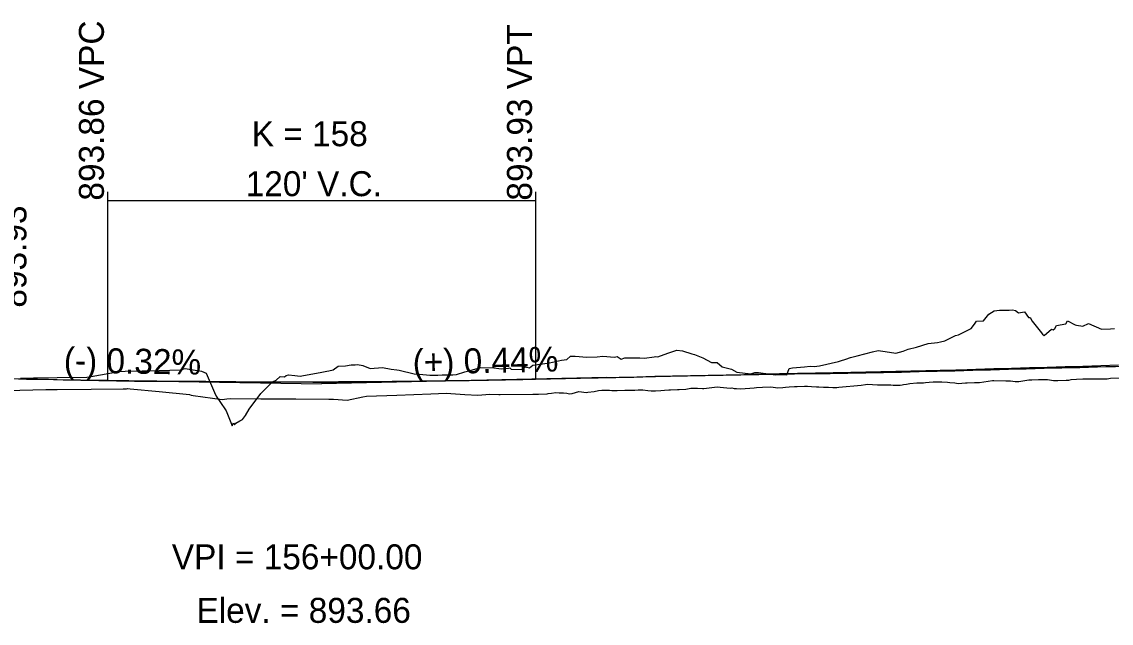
# Model space of a CAD drawing. Extents: x 1475774 to 1484571, y 1098511 to 1113011.
# Drawn here: x 1478287 to 1478592.4, y 1103912.5 to 1104081 of the extents above; entities that cross this region are included whole.
import ezdxf

# ---------------------------------------------------------------- set-up
doc = ezdxf.new("R2010")
doc.units = 0
for name, color, linetype in [('RD_DDB_GradeTX', 7, 'Continuous'), ('RD_DDB_PointTX', 7, 'Continuous'), ('RD_DDB_Profile_EX', 7, 'Continuous'), ('RD_DDB_Profile_Lbl', 7, 'Continuous'), ('RD_DDB_Profile_PR', 7, 'Continuous'), ('RD_DDB_StripGrade', 7, 'Continuous'), ('RD_DDB_VCLbl', 7, 'Continuous'), ('RD_Sketch2', 7, 'Continuous'), ('RD_Sketch3', 7, 'Continuous')]:
    doc.layers.add(name, color=color, linetype=linetype)

msp = doc.modelspace()

# ---------------------------------------------------------------- linework, layer by layer
at = {"layer": 'RD_DDB_GradeTX'}
for p in [(1478450.96, 1103981.31), (1478290.99, 1103980.85)]:
    msp.add_line(p, (1478370.98, 1103979.56), dxfattribs=at)
at = {"layer": 'RD_DDB_PointTX'}
msp.add_lwpolyline([(1478284.42, 1103981), (1478289.42, 1103980.88), (1478294.42, 1103980.81), (1478299.42, 1103980.7), (1478304.42, 1103980.58), (1478309.42, 1103980.46), (1478314.42, 1103980.34), (1478319.42, 1103980.32), (1478324.42, 1103980.3), (1478329.42, 1103980.28), (1478334.42, 1103980.26), (1478339.42, 1103980.24), (1478344.42, 1103980.14), (1478349.42, 1103980.12), (1478354.42, 1103980.1), (1478359.42, 1103980.09), (1478364.42, 1103980.07), (1478369.42, 1103980.04), (1478374.42, 1103980.02), (1478379.42, 1103980), (1478384.42, 1103980.01), (1478389.42, 1103980.1), (1478394.42, 1103980.2), (1478399.42, 1103980.3), (1478404.42, 1103980.39), (1478409.42, 1103980.48), (1478414.42, 1103980.58), (1478419.42, 1103980.68), (1478424.42, 1103980.78), (1478429.42, 1103980.88), (1478434.42, 1103980.98), (1478439.42, 1103981.09), (1478444.42, 1103981.2), (1478449.42, 1103981.31), (1478454.42, 1103981.42), (1478459.42, 1103981.54), (1478464.42, 1103981.65), (1478469.42, 1103981.76), (1478474.42, 1103981.87), (1478479.42, 1103981.98), (1478484.42, 1103982.1), (1478489.42, 1103982.2), (1478494.42, 1103982.3), (1478499.42, 1103982.4), (1478504.42, 1103982.5), (1478509.42, 1103982.6), (1478514.42, 1103982.7), (1478519.42, 1103982.79), (1478524.42, 1103982.89), (1478529.42, 1103982.99), (1478534.42, 1103983.09), (1478539.42, 1103983.22), (1478544.42, 1103983.36), (1478549.42, 1103983.51), (1478554.42, 1103983.65), (1478559.42, 1103983.8), (1478564.42, 1103983.94), (1478569.42, 1103984.09), (1478574.42, 1103984.23), (1478579.42, 1103984.38), (1478584.42, 1103984.53), (1478589.42, 1103984.69), (1478594.42, 1103984.84)], dxfattribs=at)
at = {"layer": 'RD_DDB_Profile_EX'}
msp.add_lwpolyline([(1478283.54, 1103981), (1478288.54, 1103980.88), (1478293.54, 1103980.81), (1478298.54, 1103980.7), (1478303.54, 1103980.58), (1478308.54, 1103980.46), (1478313.54, 1103980.34), (1478318.54, 1103980.32), (1478323.54, 1103980.3), (1478328.54, 1103980.28), (1478333.54, 1103980.27), (1478338.54, 1103980.25), (1478343.54, 1103980.14), (1478348.54, 1103980.12), (1478353.54, 1103980.11), (1478358.54, 1103980.09), (1478363.54, 1103980.07), (1478368.54, 1103980.03), (1478373.54, 1103980.02), (1478378.54, 1103980), (1478383.54, 1103980), (1478388.54, 1103980.09), (1478393.54, 1103980.19), (1478398.54, 1103980.28), (1478403.54, 1103980.38), (1478408.54, 1103980.45), (1478413.54, 1103980.55), (1478418.54, 1103980.64), (1478423.54, 1103980.74), (1478428.54, 1103980.83), (1478433.54, 1103980.91), (1478438.54, 1103981.01), (1478443.54, 1103981.12), (1478448.54, 1103981.23), (1478453.54, 1103981.33), (1478458.54, 1103981.44), (1478463.54, 1103981.55), (1478468.54, 1103981.65), (1478473.54, 1103981.76), (1478478.54, 1103981.86), (1478483.54, 1103981.97), (1478488.54, 1103982.04), (1478493.54, 1103982.13), (1478498.54, 1103982.23), (1478503.54, 1103982.32), (1478508.54, 1103982.42), (1478513.54, 1103982.48), (1478518.54, 1103982.57), (1478523.54, 1103982.66), (1478528.54, 1103982.75), (1478533.54, 1103982.85), (1478538.54, 1103982.96), (1478543.54, 1103983.1), (1478548.54, 1103983.23), (1478553.54, 1103983.36), (1478558.54, 1103983.5), (1478563.54, 1103983.63), (1478568.54, 1103983.76), (1478573.54, 1103983.89), (1478578.54, 1103984.02), (1478583.54, 1103984.15), (1478588.54, 1103984.3), (1478593.54, 1103984.44)], dxfattribs=at)
at = {"layer": 'RD_DDB_Profile_PR'}
for p, q in [((1478430.98, 1103980.88), (1479020.98, 1103993.81)), ((1478430.98, 1103980.88), (1479020.98, 1103993.81)), ((1478288.27, 1103980.89), (1478310.98, 1103980.53)), ((1478288.27, 1103980.89), (1478310.98, 1103980.53))]:
    msp.add_line(p, q, dxfattribs=at)
msp.add_spline([(1478310.98, 1103980.53), (1478313.38, 1103980.49), (1478315.78, 1103980.45), (1478318.18, 1103980.42), (1478320.58, 1103980.39), (1478322.98, 1103980.36), (1478325.38, 1103980.33), (1478327.78, 1103980.3), (1478330.18, 1103980.28), (1478332.58, 1103980.25), (1478334.98, 1103980.23), (1478337.38, 1103980.21), (1478339.78, 1103980.19), (1478342.18, 1103980.18), (1478344.58, 1103980.16), (1478346.98, 1103980.15), (1478349.38, 1103980.14), (1478351.78, 1103980.13), (1478354.18, 1103980.13), (1478356.58, 1103980.12), (1478358.98, 1103980.12), (1478361.38, 1103980.12), (1478363.78, 1103980.12), (1478366.18, 1103980.12), (1478368.58, 1103980.12), (1478370.98, 1103980.13), (1478373.38, 1103980.14), (1478375.78, 1103980.15), (1478378.18, 1103980.16), (1478380.58, 1103980.17), (1478382.98, 1103980.19), (1478385.38, 1103980.21), (1478387.78, 1103980.22), (1478390.18, 1103980.24), (1478392.58, 1103980.27), (1478394.98, 1103980.29), (1478397.38, 1103980.32), (1478399.78, 1103980.35), (1478402.18, 1103980.38), (1478404.58, 1103980.41), (1478406.98, 1103980.44), (1478409.38, 1103980.48), (1478411.78, 1103980.51), (1478414.18, 1103980.55), (1478416.58, 1103980.59), (1478418.98, 1103980.63), (1478421.38, 1103980.68), (1478423.78, 1103980.73), (1478426.18, 1103980.77), (1478428.58, 1103980.82), (1478430.98, 1103980.88)], degree=3, dxfattribs=at)
msp.add_spline([(1478310.98, 1103980.53), (1478313.38, 1103980.49), (1478315.78, 1103980.45), (1478318.18, 1103980.42), (1478320.58, 1103980.39), (1478322.98, 1103980.36), (1478325.38, 1103980.33), (1478327.78, 1103980.3), (1478330.18, 1103980.28), (1478332.58, 1103980.25), (1478334.98, 1103980.23), (1478337.38, 1103980.21), (1478339.78, 1103980.19), (1478342.18, 1103980.18), (1478344.58, 1103980.16), (1478346.98, 1103980.15), (1478349.38, 1103980.14), (1478351.78, 1103980.13), (1478354.18, 1103980.13), (1478356.58, 1103980.12), (1478358.98, 1103980.12), (1478361.38, 1103980.12), (1478363.78, 1103980.12), (1478366.18, 1103980.12), (1478368.58, 1103980.12), (1478370.98, 1103980.13), (1478373.38, 1103980.14), (1478375.78, 1103980.15), (1478378.18, 1103980.16), (1478380.58, 1103980.17), (1478382.98, 1103980.19), (1478385.38, 1103980.21), (1478387.78, 1103980.22), (1478390.18, 1103980.24), (1478392.58, 1103980.27), (1478394.98, 1103980.29), (1478397.38, 1103980.32), (1478399.78, 1103980.35), (1478402.18, 1103980.38), (1478404.58, 1103980.41), (1478406.98, 1103980.44), (1478409.38, 1103980.48), (1478411.78, 1103980.51), (1478414.18, 1103980.55), (1478416.58, 1103980.59), (1478418.98, 1103980.63), (1478421.38, 1103980.68), (1478423.78, 1103980.73), (1478426.18, 1103980.77), (1478428.58, 1103980.82), (1478430.98, 1103980.88)], degree=3, dxfattribs=at)
at = {"layer": 'RD_DDB_VCLbl'}
for p, q in [((1478310.98, 1104033.38), (1478310.98, 1103980.53)), ((1478430.98, 1104033.38), (1478430.98, 1103980.88)), ((1478310.98, 1104030.88), (1478430.98, 1104030.88))]:
    msp.add_line(p, q, dxfattribs=at)
at = {"layer": 'RD_Sketch2'}
msp.add_lwpolyline([(1478282.81, 1103977.7), (1478293.71, 1103977.91), (1478296.87, 1103977.94), (1478306.4, 1103978.03), (1478315.37, 1103978.12), (1478315.92, 1103978.15), (1478316.31, 1103978.17), (1478316.62, 1103978.2), (1478317.37, 1103978.11), (1478325.45, 1103977.36), (1478333.97, 1103976.57), (1478334.46, 1103976.38), (1478334.97, 1103976.31), (1478343.14, 1103975.18), (1478344.49, 1103975.3), (1478345.56, 1103975.4), (1478354.02, 1103975.36), (1478363.8, 1103975.31), (1478373.07, 1103975.27), (1478374.34, 1103975.26), (1478378.15, 1103975.01), (1478382.59, 1103975.88), (1478383.59, 1103976.07), (1478392.12, 1103976.39), (1478401.64, 1103976.76), (1478405.95, 1103976.92), (1478411.16, 1103976.59), (1478414.8, 1103976.37), (1478418.18, 1103976.66), (1478420.69, 1103976.53), (1478421.07, 1103976.51), (1478430.21, 1103976.64), (1478431.77, 1103976.67), (1478434.2, 1103976.76), (1478434.54, 1103976.79), (1478435.45, 1103976.9), (1478436.68, 1103977.1), (1478437.58, 1103977.05), (1478438.83, 1103977.06), (1478439.74, 1103976.91), (1478440.55, 1103976.78), (1478441.27, 1103976.82), (1478443.12, 1103977.35), (1478445.26, 1103977.14), (1478445.67, 1103977.17), (1478447.41, 1103977.39), (1478448.66, 1103977.69), (1478449.55, 1103977.8), (1478450.78, 1103977.81), (1478451.7, 1103977.79), (1478452.35, 1103977.69), (1478453.84, 1103977.68), (1478456.05, 1103977.77), (1478458.13, 1103977.74), (1478458.79, 1103977.78), (1478459.74, 1103977.84), (1478460.28, 1103977.86), (1478461.02, 1103977.84), (1478462.42, 1103977.71), (1478463.43, 1103977.59), (1478464.57, 1103977.54), (1478466.15, 1103977.67), (1478467.12, 1103977.8), (1478468.31, 1103977.86), (1478468.86, 1103977.88), (1478470.81, 1103977.92), (1478471.27, 1103977.94), (1478473.15, 1103978.07), (1478474.5, 1103978.3), (1478476.4, 1103978.28), (1478477.83, 1103978.26), (1478478.19, 1103978.26), (1478481.87, 1103978.66), (1478482.72, 1103978.57), (1478485.56, 1103978.36), (1478486.03, 1103978.38), (1478486.68, 1103978.27), (1478487.36, 1103978.26), (1478488.58, 1103978.18), (1478492.26, 1103978.46), (1478492.93, 1103978.54), (1478494.61, 1103978.59), (1478496.96, 1103978.69), (1478498.9, 1103978.45), (1478500.29, 1103978.56), (1478501.05, 1103978.59), (1478502.11, 1103978.72), (1478503.57, 1103978.84), (1478503.89, 1103978.84), (1478504.37, 1103978.83), (1478506.41, 1103978.9), (1478507.19, 1103978.86), (1478508.33, 1103978.8), (1478509.79, 1103978.72), (1478510.38, 1103978.68), (1478511.75, 1103978.61), (1478512.13, 1103978.59), (1478513.13, 1103978.57), (1478514.32, 1103978.54), (1478515.4, 1103978.49), (1478516.05, 1103978.57), (1478522.31, 1103979.2), (1478523.47, 1103979.36), (1478524.03, 1103979.42), (1478525.46, 1103979.32), (1478526.88, 1103979.25), (1478527.73, 1103979.3), (1478529.02, 1103979.25), (1478530.57, 1103979.23), (1478531.28, 1103979.14), (1478533.2, 1103979.19), (1478533.77, 1103979.27), (1478534.15, 1103979.31), (1478534.98, 1103979.44), (1478535.91, 1103979.59), (1478537.88, 1103979.78), (1478539.78, 1103979.82), (1478540.33, 1103979.92), (1478541.34, 1103980.03), (1478542.47, 1103980.1), (1478544.85, 1103980.12), (1478546.48, 1103979.99), (1478547.16, 1103979.92), (1478548.54, 1103979.78), (1478549.44, 1103979.67), (1478551.5, 1103979.86), (1478551.96, 1103979.83), (1478554.03, 1103979.96), (1478555.43, 1103979.94), (1478559.1, 1103980.5), (1478559.49, 1103980.5), (1478562.78, 1103980.37), (1478563.55, 1103980.39), (1478564.12, 1103980.41), (1478565.48, 1103980.24), (1478566.44, 1103980.19), (1478569.31, 1103980.62), (1478570.1, 1103980.69), (1478572, 1103980.74), (1478573.08, 1103980.73), (1478574.51, 1103980.73), (1478576.22, 1103980.52), (1478577.43, 1103980.49), (1478579.7, 1103980.59), (1478580.52, 1103980.61), (1478581.1, 1103980.74), (1478582.6, 1103980.82), (1478584.43, 1103980.92), (1478584.78, 1103980.93), (1478585.24, 1103980.94), (1478590.1, 1103980.92), (1478591.27, 1103980.97), (1478592.13, 1103981.1), (1478595.31, 1103981.22)], dxfattribs=at)
at = {"layer": 'RD_Sketch3'}
msp.add_lwpolyline([(1478286.63, 1103981.15), (1478290.24, 1103981.24), (1478290.67, 1103981.24), (1478291.35, 1103981.25), (1478296.87, 1103981.31), (1478305.18, 1103981.4), (1478306.4, 1103981.61), (1478314.23, 1103983.02), (1478315.92, 1103983.06), (1478325.45, 1103983.29), (1478331.44, 1103983.44), (1478332.77, 1103983.86), (1478334.97, 1103983.49), (1478337.3, 1103983.1), (1478338.68, 1103982.49), (1478340.99, 1103977.14), (1478341.45, 1103976.08), (1478342.5, 1103974.62), (1478344.27, 1103971.96), (1478345.92, 1103967.75), (1478346.27, 1103968.57), (1478346.61, 1103968.02), (1478347, 1103968.48), (1478348.08, 1103969.13), (1478348.81, 1103969.57), (1478349.64, 1103970.68), (1478350.68, 1103972.42), (1478354.02, 1103976.83), (1478354.49, 1103977.3), (1478355.23, 1103978), (1478357.28, 1103980.13), (1478358.29, 1103980.54), (1478359.38, 1103981.59), (1478360.62, 1103981.54), (1478361.08, 1103981.88), (1478361.69, 1103982.02), (1478363.54, 1103981.86), (1478364.97, 1103981.73), (1478365.96, 1103981.84), (1478370.62, 1103982.73), (1478372.5, 1103983.1), (1478373.07, 1103983.21), (1478374.24, 1103983.43), (1478375.64, 1103984.47), (1478377.71, 1103984.6), (1478379.31, 1103984.83), (1478380.45, 1103984.87), (1478381.05, 1103984.92), (1478382.59, 1103984.67), (1478384.65, 1103983.88), (1478388.12, 1103984.16), (1478390.53, 1103983.61), (1478392.12, 1103983.43), (1478392.73, 1103983.37), (1478396.97, 1103982.34), (1478398.46, 1103982.27), (1478401.31, 1103981.94), (1478401.64, 1103981.95), (1478403.59, 1103982.01), (1478404.77, 1103982.06), (1478407.79, 1103982.05), (1478408.84, 1103982.19), (1478411.16, 1103982.88), (1478412.27, 1103983.21), (1478413.95, 1103983.65), (1478415.6, 1103984.13), (1478419.3, 1103984.03), (1478420.69, 1103983.86), (1478421.38, 1103983.77), (1478423.41, 1103983.92), (1478423.74, 1103984.02), (1478424.18, 1103983.68), (1478427.12, 1103983.59), (1478428.04, 1103984.3), (1478429.3, 1103984.02), (1478430.22, 1103984.75), (1478434.87, 1103985.39), (1478438.26, 1103986.16), (1478439.74, 1103986.38), (1478440.83, 1103987.25), (1478442.1, 1103987.28), (1478445.35, 1103987.06), (1478448.27, 1103987.08), (1478449.81, 1103987.26), (1478453.09, 1103986.97), (1478453.87, 1103987.17), (1478454.95, 1103986.43), (1478456.05, 1103986.87), (1478456.37, 1103986.85), (1478458.79, 1103986.81), (1478460.21, 1103986.79), (1478461.56, 1103986.74), (1478464.2, 1103987.11), (1478464.63, 1103987.16), (1478465.23, 1103987.12), (1478467.07, 1103987.77), (1478468.31, 1103988.2), (1478470.63, 1103989.01), (1478472.14, 1103988.83), (1478474.76, 1103987.98), (1478475.52, 1103987.75), (1478477.86, 1103986.86), (1478480.32, 1103985.5), (1478481.88, 1103985.55), (1478483.27, 1103984.34), (1478485.91, 1103983.61), (1478487.43, 1103982.82), (1478491.32, 1103982.38), (1478492.42, 1103982.72), (1478493.48, 1103982.71), (1478496.88, 1103982.28), (1478498.38, 1103982.1), (1478499.39, 1103982.17), (1478501.39, 1103982.1), (1478502.11, 1103983.8), (1478503.01, 1103983.98), (1478506.41, 1103984.32), (1478508, 1103984.48), (1478509.06, 1103984.43), (1478510.59, 1103984.54), (1478515.93, 1103985.84), (1478516.51, 1103985.99), (1478517.98, 1103986.5), (1478519.3, 1103986.92), (1478521.1, 1103987.43), (1478525.46, 1103988.47), (1478527, 1103988.84), (1478529.02, 1103988.56), (1478531.99, 1103988.18), (1478534.06, 1103988.68), (1478534.98, 1103989.07), (1478535.45, 1103989.27), (1478537.76, 1103989.82), (1478541.08, 1103990.86), (1478543.69, 1103991.09), (1478544.5, 1103991.3), (1478545.72, 1103991.63), (1478548.67, 1103993.07), (1478549.52, 1103993.29), (1478553.1, 1103995.06), (1478554.03, 1103996.3), (1478554.61, 1103997.09), (1478556.6, 1103997.15), (1478558.02, 1103999.04), (1478559.52, 1104000.04), (1478561, 1104000.21), (1478563.74, 1104000.15), (1478564.71, 1104000.31), (1478565.56, 1104000.06), (1478566.36, 1103999.44), (1478568.04, 1103999.68), (1478569.19, 1103998.17), (1478569.61, 1103998.14), (1478570.21, 1103997.14), (1478572.47, 1103994.27), (1478573.08, 1103993.42), (1478573.53, 1103993.06), (1478575.63, 1103994.82), (1478576.09, 1103994.67), (1478576.54, 1103995.06), (1478576.98, 1103995.85), (1478579.65, 1103996.35), (1478580.12, 1103997.16), (1478582.27, 1103996.07), (1478582.6, 1103996.01), (1478584.39, 1103995.69), (1478585.95, 1103996.44), (1478589.66, 1103994.86), (1478592.13, 1103994.95), (1478593.3, 1103995.01)], dxfattribs=at)

# ---------------------------------------------------------------- texts
at = {"layer": 'RD_DDB_GradeTX'}
for s, rotation, p in [('(-) 0.32%', 359.078, (1478298.71, 1103982.72)), ('(+) 0.44%', 1.2555, (1478396.61, 1103982.12))]:
    msp.add_text(s, height=7, rotation=rotation, dxfattribs=at).set_placement(p)
at = {"layer": 'RD_DDB_Profile_Lbl'}
msp.add_text('893.93', height=7, rotation=90, dxfattribs=at).set_placement((1478288.27, 1104000.89))
for s, p in [('VPI = 156+00.00', (1478329.02, 1103927.56)), ('Elev. = 893.66', (1478335.93, 1103912.56))]:
    msp.add_text(s, height=7, dxfattribs=at).set_placement(p)
at = {"layer": 'RD_DDB_StripGrade'}
for s, p in [('893.86 VPC', (1478309.98, 1104030.88)), ('893.93 VPT', (1478429.98, 1104030.88))]:
    msp.add_text(s, height=7, rotation=90, dxfattribs=at).set_placement(p)
at = {"layer": 'RD_DDB_VCLbl'}
for s, p in [('K = 158', (1478351.43, 1104046.13)), ("120' V.C.", (1478349.73, 1104032.13))]:
    msp.add_text(s, height=7, dxfattribs=at).set_placement(p)

doc.saveas('drawing.dxf')
